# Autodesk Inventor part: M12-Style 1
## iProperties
Created: 2006-02
Material: Steel, Mild
Description: Hex Nut
Document SubType Name: Modeling
Standard: ANSI B 18.2.4.1 M
Designer: Administrator
Standards Organization: ANSI
Language: en-US
Categories: <MemberInstance><Categories><Category DisplayName="Fasteners" InternalName="e4da775c-781d-43d5-af7c-5136215cf5a6" Mnemonic="FSTN"><Category DisplayName="Nuts" I
Density: 1 g/cm^3
Author: Administrator
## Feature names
1. Body [Extrusion]
2. Chamfer1 [Revolution]
3. Thread [Hole]
4. Chamfer2
5. Chamfer3
